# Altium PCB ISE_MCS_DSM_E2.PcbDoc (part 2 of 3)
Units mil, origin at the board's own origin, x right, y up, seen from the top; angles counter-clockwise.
Board outline 7874.02 x 2559.06 mil, 4 copper layers (Top Layer, MidLayer1, MidLayer2, Bottom Layer), stack 61.2 mil thick; 400 components, 190 nets, 1028 pads, 191 vias.
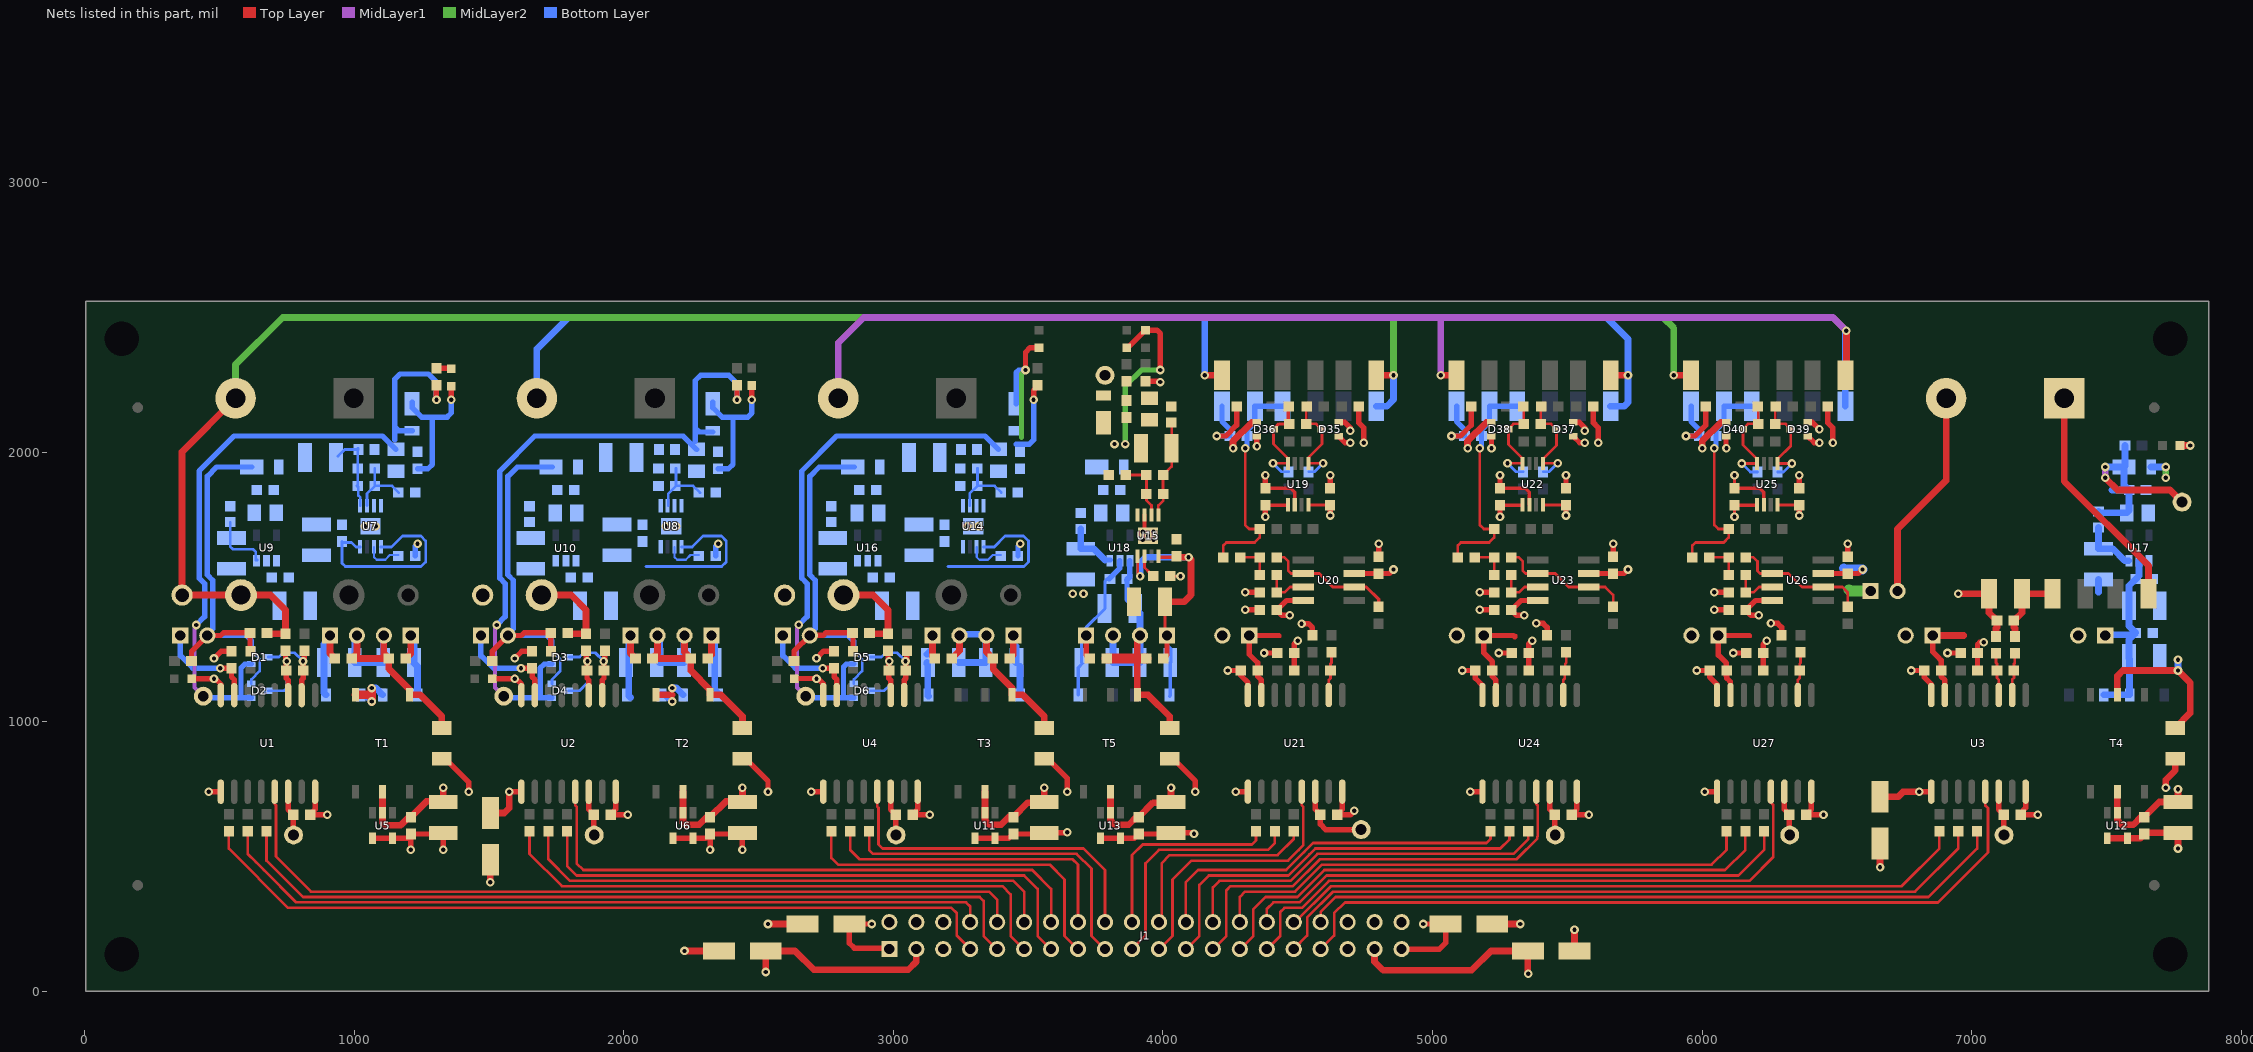
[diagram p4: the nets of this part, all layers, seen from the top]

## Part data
C1 C2 C8 C9 C32 C64: "CAP, AL, 22uF, 25V, +/-20%, 0.76 ohm, SMD"
C3 C7 C13 C15 C112 C124 C136: library part 06033C104JAT2A, "CAP, CERM, 0.1uF, 25V, +/-5%, X7R, 0603"
C4 C10 C17 C114 C126 C138: "CAP, CERM, 3900pF, 25V, +/-5%, C0G/NP0, 0603"
C5 C6 C11 C12 C14 C16 C18 C19 C20 C21 C26 C27 C29 C31 C34 C36 C41 C43 C44 C46 C53 C54 C59 C60 C68 C69 C70 C72 C74 C76 C78 C80 C85 C87 C88 C90 C97 C98 C104 C105 C106 C109 C110 C111 C115 C116 C118 C119 C120 C121 C122 C123 C127 C128 C130 C131 C132 C133 C134 C135 C139 C140 C142 C143 C144 C145: library part C0603C104K5RACTU, "CAP, CERM, 0.1uF, 50V, +/-10%, X7R, 0603"
C22 C23 C61 C62 C63: library part 202R18W102KV4E, "CAP, CERM, 1000pF, 2KV 10% X7R 1206"
C24 C25 C28 C30 C33 C35 C37 C39 C47 C48 C55 C56 C57 C58 C65 C66 C67 C71 C73 C75 C77 C79 C81 C83 C91 C92 C99 C100 C101 C102 C107 C108: library part GMK325AB7106MM-T, "CAP, CERM, 10uF, 35V, +/-20%, X7R, 1210"
C38 C40 C51 C52 C82 C84 C95 C96 C103: library part C2012X5R1H475K125AB, "CAP, CERM, 4.7uF, 50V, +/-10%, X5R, 0805"
C42 C45 C49 C50 C86 C89 C93 C94: library part 06031C103JAT2A, "CAP, CERM, 0.01uF, 100V, +/-5%, X7R, 0603"
C113 C117 C125 C129 C137 C141: library part 06031C472KAT2A, "CAP, CERM, 4700pF, 100V, +/-10%, X7R, 0603"
D1 D2 D3 D4 D5 D6 D35 D36 D37 D38 D39 D40: library part BAV99WT1G, "Diode, P-N, 70V, 0.2A, SOT-323"
D7 D8 D9 D10 D19 D20 D21 D22 D23 D24: "Diode, Schottky, 20V, 0.5A, SOD-123"
D11 D12 D15 D16 D25 D26 D29 D30 D31: library part DFLZ6V2-7, "Diode, Zener, 6.2V, 1W, PowerDI123"
D13 D14 D17 D18 D27 D28 D32 D33 D34: library part "LED_LG L29K-G2J1-24-Z", "LED SmartLED Green 570NM"
FB1 FB2 FB3 FB4 FB5 FB6 FB7 FB8 FB9: library part MMZ1608B102C, "FERRITE CHIP 1000 OHM 300MA 0603"
FID1 FID2 FID3 FID4 FID5 FID6 FID7 FID8: library part Fiducial, "Fiducial mark.  There is nothing to buy or mount."
J1: library part CONN_61304021021, "Connector, Right Angle 2x20 pin, 100mil spacing"
J2 J4 J6 J8: "Terminal Block, 4x1, 2.54mm, TH"
J3 J5 J7 J9 J10 J11 J12 J13 J14 J15 J16 J17 J18 J19 J20 J21 J22: library part JUMPER_2X100MIL, "Header, Male 2-pin, 100mil spacing,"
LBL1: library part THT-14-423-10, "Thermal Transfer Printable Labels, 0.650\" W x 0.200\" H - 10,000 per roll"
Logo1: library part TI_Logo, "Texas Instrument Corporate Signature"
MH1 MH2 MH3 MH4: library part "NY PMS 440 0025 PH", "Mountin hole, NPTH Drill 3.2mm"
R1 R4 R9 R12 R20 R29: "RES, 100 ohm, 1%, 0.1W, 0603"
R2 R10 R23: "RES 50mOHM 3W .5% TO-247 TH"
R3 R11 R24: library part RES_PWR4413DR050F, "RES METAL .005 OHM 5W 1% RADIAL"
R5 R6 R13 R14 R25 R26 R30 R31 R54 R57 R59 R63 R65 R67 R69 R72 R78 R81 R83 R85 R89 R91 R93 R96 R102 R105 R107 R109 R113 R115 R117 R120: library part CRCW06030000Z0EA, "RES, 0 ohm, 5%, 0.1W, 0603"
R7 R8 R15 R16 R27 R28 R32 R33 R73 R74 R97 R98 R121 R122: library part CRCW060310R0FKEA, "RES, 10.0 ohm, 1%, 0.1W, 0603"
R17 R18 R51 R52 R55 R70 R75 R76 R79 R94 R99 R100 R103 R118: library part RES_KTR25JZPF2204, "RES 2.2M OHM 1/3W 1% 1210"
R19 R60 R84 R108: "RES, 0 ohm, 5%, 0.1W, 0603"
R21 R61 R68 R87 R92 R111 R116: library part RES_KTR25JZPF2001, "RES 2K OHM 1/3W 1% 1210"
R22: "RES, 2.00k ohm, 0.5%, 0.1W, 0603"
R34 R35 R40 R41 R42 R43 R48 R49 R50: library part CRCW06033K90JNEA, "RES, 3.9k ohm, 5%, 0.1W, 0603"
R36 R37 R44 R45: library part RT0603BRD0737KL, "RES, 37.0k ohm, 0.1%, 0.1W, 0603"
R38 R39 R46 R47: library part CRCW060311K5FKEA, "RES, 11.5k ohm, 1%, 0.1W, 0603"
R53 R71 R77 R95 R101 R119: library part RC0603FR-0747KL, "RES 15.0K OHM 1/10W .1% SMD 0603"
R56 R66 R80 R90 R104 R114: "RES, 56.0 ohm, 1%, 0.1W, 0603"
R58 R82 R106: library part RC0603FR-071KL, "RES, 1.00k ohm, 1%, 0.1W, 0603"
R62 R64 R86 R88 R110 R112: library part RC0603FR-074K7L, "RES, 4.70k ohm, 1%, 0.1W, 0603"
T1 T2 T3 T4 T5: "Transformer 475uH SMD"
TP1 TP2 TP3 TP4 TP5 TP6 TP7 TP8 TP9 TP10 TP11 TP12: library part TP-040_RND, "Test Point, O.040 Hole"
U1 U2 U3 U4 U21 U24 U27: "20 MHz, Isolated Delta-Sigma Modulator, LVDS interface:"
U5 U6 U11 U12 U13: "Transformer Driver for Isolated Power Supplies, DBV0005A"
U7: "-36V, -200mA, Ultralow-Noise, Negative Linear Regulator"
U8 U14 U15: library part TPS7A3001DGNR, "-36V, -200mA, Ultralow-Noise, Negative Linear Regulator"
U9 U10 U16 U17 U18: "Regulator, LDO, 5V, 0.15A, SOT23-5"
U19 U22 U25: "IC, Precision, 200uA, 36V Supply Instrument Amplifier."
U20 U23 U26: library part OPA211AID, "IC, 1.1nV/vHz Noise, Low Power, Precision OpAmp"
ZZ1: library part AssemblyNoteLabel, "This Assembly Note is for PCB labels only"
ZZ2: library part AssemblyNote, "These assemblies are ESD sensitive, ESD precautions shall be observed."
ZZ3: library part AssemblyNote, "These assemblies must be clean and free from flux and all contaminants. Use of no clean flux is not acceptable."
ZZ4: library part AssemblyNote, "These assemblies must comply with workmanship standards IPC-A-610 Class 2, unless otherwise specified."

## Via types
v1: diameter 32, hole 16, Top Layer to Bottom Layer, tented both sides, 191 vias

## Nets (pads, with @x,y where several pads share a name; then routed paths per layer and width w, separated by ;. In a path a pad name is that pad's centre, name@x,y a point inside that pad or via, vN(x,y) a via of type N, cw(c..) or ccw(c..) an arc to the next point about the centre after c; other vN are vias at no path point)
+3.3V_DVDD: C1.1 C3.2 C7.2 C9.1 C13.2 C15.2 C112.2 C124.2 C136.2 J1.1 J1.39 TP1.1 TP2.1 TP3.1 TP4.1 TP10.1 TP11.1 TP12.1 U1.14 U2.14 U3.14 U4.14 U21.14 U24.14 U27.14 | length 1942.7
  Top Layer w20: U1.14@755,740.55 755,675 C3.2@775,655 ; C3.2@773.5,655 773.5,586.5 TP1.1@780,580 ; U2.14@1870,740.55 1870,675 C7.2@1890,655 ; C7.2@1888.5,655 1888.5,586.5 TP2.1@1890,585 ; v1(2920,250) C1.1@2836.61,250 2836.61,178.39 2855,160 2981.7,160 J1.1@2985.01,156.69 ; U4.14@2990,740.87 2990,675 C15.2@3010,655 ; C15.2@3008.5,655 3008.5,581.5 TP4.1@3010,580 ; U21.14@4565,740.87 4565,675 C112.2@4585,655 ; C112.2@4583.5,655 4583.5,620 4603.5,600 TP10.1@4735,600 ; J1.39@4885.01,156.69 5025,156.69 5048.39,180.08 C9.1@5048.39,250 v1(4965,250) ; U24.14@5435,740.87 5435,675 C124.2@5455,655 ; C124.2@5453.5,655 5453.5,581.5 TP11.1@5455,580 ; U27.14@6305,740.87 6305,675 C136.2@6325,655 ; C136.2@6323.5,655 6323.5,581.5 TP12.1@6325,580 ; U3.14@7100,740.87 7100,675 C13.2@7120,655 ; C13.2@7118.5,655 7118.5,581.5 TP3.1@7120,580
+5.0V_PH: C103.2 C106.1 C110.2 C111.2 C121.1 C122.2 C123.2 C133.1 C134.2 C135.2 C145.1 D31.1 D35.2 D36.2 D37.2 D38.2 D39.2 D40.2 FB9.2 J20.2 J21.2 J22.2 R50.2 R72.1 R96.1 R120.1 U19.8 U20.7 U22.8 U23.7 U25.8 U26.7 | length 1606.4
  Top Layer w12: U19.8@4540,1804.4 4619.1,1804.4 C110.2@4620,1803.5 ; U22.8@5410,1804.4 C122.2@5489.1,1804.4 ; C122.2@5494.1,1804.4 C122.2@5495,1803.5 ; U25.8@6280,1804.4 6359.1,1804.4 C134.2@6360,1803.5
  Top Layer w20: R50.2@3935,2263.5 3988.5,2263.5 3990,2265 v1(3990,2260) ; v1(4348.5,2021.5) D36.2@4348.5,2059.41 ; R72.1@4486.5,1190 C121.1@4486.5,1255 4486.5,1288.5 4497.99,1300 v1(4500,1300) ; v1(4620,1765) C110.2@4620,1803.5 ; D35.2@4651.5,2110.59 4674.41,2110.59 4695,2090 v1(4695,2080) ; U20.7@4709,1550 4840,1550 v1(4855,1565) ; v1(5218.5,2015) D38.2@5218.5,2059.41 ; R96.1@5356.5,1190 C133.1@5356.5,1255 5356.5,1288.5 5367.99,1300 v1(5370,1300) ; v1(5495,1765) C122.2@5495,1803.5 ; D37.2@5521.5,2110.59 5544.41,2110.59 5565,2090 v1(5565,2080) ; U23.7@5579,1550 5710,1550 v1(5725,1565) ; D40.2@6088.5,2059.41 6088.5,2021.5 6085,2017.99 6085,2015 v1(6090,2015) ; R120.1@6226.5,1190 C145.1@6226.5,1255 6226.5,1286.5 v1(6240,1300) ; v1(6360,1765) C134.2@6360,1803.5 ; D39.2@6391.5,2110.59 6409.41,2110.59 v1(6435,2085) ; U26.7@6449,1550 6580,1550 v1(6595,1565)
  Bottom Layer w36: 6525,1570 6530,1565 v1(6595,1565)
+5.0V_USH: C6.1 C51.2 C53.1 D1.2 D2.2 D15.1 FB3.2 J3.2 R6.1 R40.2 | length 1491.7
  Top Layer w20: R40.2@396.5,1225 396.5,1261.5 J3.2@455,1320 505,1320 515,1330 C6.1@613.5,1330 ; C6.1@613.5,1320 613.5,1262.99 R6.1@615,1261.5
  Bottom Layer w10: D2.2@618.5,1140.59 618.5,1156.85 649.25,1187.6 649.25,1232.43 618.5,1263.18 D1.2@618.5,1265.59
  Bottom Layer w20: J3.2@450,1320 J3.2@455,1325 ; D1.2@618.5,1265.59 618.5,1301.5 600,1320 J3.2@455,1320 J3.2@455,1325 ; D15.1@620,1945 D15.1@619.81,1945 490,1945 455,1910 455,1545 475,1525 475,1345 J3.2@455,1325
+5.0V_VDC: C19.1 C96.2 C98.1 D30.1 FB8.2 J9.2 R26.1 R49.2 TP9.1 | length 988.8
  Top Layer w20: R26.1@7021.5,1190 C19.1@7021.5,1255 7021.5,1286.5 7030,1295 v1(7045,1295)
  Top Layer w25: v1(7495,1905) 7540,1860 7735,1860 TP9.1@7780,1815
  MidLayer1 w25: v1(7495,1905) v1(7495,1945)
  Bottom Layer w25: FB8.2@7470,1779.53 7474.53,1775 C96.2@7575,1775 7583.5,1783.5 C98.1@7583.5,1860 ; v1(7495,1945) D30.1@7564.8,1945 ; 7520,1860 C98.1@7583.5,1860 ; R49.2@7568.5,2025 7568.5,1948.7 D30.1@7564.8,1945 ; D30.1@7564.8,1945 7564.8,1878.7 C98.1@7583.5,1860
+5.0V_VSH: C12.1 C52.2 C54.1 D3.2 D4.2 D16.1 FB4.2 J5.2 R14.1 R41.2 | length 1484.4
  Top Layer w20: R41.2@1511.5,1225 1511.5,1261.5 J5.2@1570,1320 1620,1320 1630,1330 C12.1@1728.5,1330 ; C12.1@1728.5,1320 1728.5,1262.99 R14.1@1730,1261.5
  Bottom Layer w10: D4.2@1733.5,1140.59 1733.5,1156.85 1764.25,1187.6 1764.25,1232.43 1733.5,1263.18 D3.2@1733.5,1265.59
  Bottom Layer w20: D3.2@1733.5,1265.59 1733.5,1301.5 1715,1320 J5.2@1570,1320 1570,1325 1590,1345 1590,1525 1570,1545 1570,1910 1605,1945 D16.1@1734.81,1945
+5.0V_WSH: C21.1 C95.2 C97.1 D5.2 D6.2 D29.1 FB7.2 J10.2 R31.1 R48.2 | length 1485.6
  Top Layer w20: R48.2@2631.5,1225.31 2631.5,1261.81 2690,1320.31 2740,1320.31 2750,1330.31 C21.1@2848.5,1330.31 ; R31.1@2850,1261.5 C21.1@2850,1328.5
  Bottom Layer w10: D6.2@2853.5,1140.59 2853.5,1156.85 2884.25,1187.6 2884.25,1232.43 2853.5,1263.18 D5.2@2853.5,1265.59
  Bottom Layer w20: J10.2@2690,1320 2832.01,1320 2853.5,1298.5 D5.2@2853.5,1265.59 ; J10.2@2690,1325 2710,1345 2710,1525 2690,1545 2690,1910 2725,1945 D29.1@2854.81,1945
+5V_CNTL: C2.1 C8.1 C24.2 C25.2 C26.2 C27.2 C32.1 C64.1 C65.2 C66.2 C67.2 C68.2 C69.2 C70.2 J1.3 J1.37 T1.2 T2.2 T3.2 T4.2 T5.2 U5.2 U6.2 U11.2 U12.2 U13.2 | length 3766.9
  Top Layer w25: T1.2@1105,740 U5.2@1105,662.24 1105,625 1113.44,616.56 1172.85,616.56 1201.29,645 C26.2@1205,645 ; C26.2@1210,646.5 1268.5,705 C24.2@1330,705 ; C24.2@1330,702.09 C24.2@1330,705 ; v1(1330,755) C24.2@1330,705 ; v1(1505,405) C32.1@1505,488.39 ; T2.2@2220,740 U6.2@2220,662.24 2220,625 2226.91,618.09 2279.52,618.09 2307.92,646.5 C27.2@2320,646.5 2378.5,705 C25.2@2440,705 ; C25.2@2440,702.09 C25.2@2440,705 ; v1(2440,755) C25.2@2440,705 ; v1(2526.61,71.61) C2.1@2526.61,150 2635,150 2705,80 3055,80 3085.01,110.01 J1.3@3085.01,156.69 ; T3.2@3340,740 U11.2@3340,662.24 3340,633.38 3355.29,618.09 3399.52,618.09 3427.92,646.5 C68.2@3441.5,646.5 ; C68.2@3445,650 C68.2@3441.5,646.5 ; C65.2@3560,700 3498.5,700 C68.2@3445,646.5 C68.2@3441.5,646.5 ; C65.2@3560,702.09 v1(3560,755) ; T5.2@3805,740 U13.2@3805,662.24 3805,635 3807.11,632.89 3807.11,631.27 3820.29,618.09 3873.09,618.09 3901.5,646.5 C70.2@3910,646.5 3963.5,700 C67.2@4030,700 ; C67.2@4030,702.09 v1(4030,755) ; J1.37@4785.01,156.69 4785.01,109.99 4816.61,78.39 5145,78.39 5216.61,150 C8.1@5353.39,150 5353.39,66.61 v1(5355,65) ; v1(6660,460) C64.1@6660,548.39 ; T4.2@7540,740 U12.2@7540,662.24 7540,633.38 7555.29,618.09 7599.52,618.09 7627.92,646.5 C69.2@7640,646.5 7695.59,702.09 C66.2@7765,702.09 v1(7765,750)
  Bottom Layer w25: v1@2525,70 v1(2526.61,71.61)
+6V_PH: C75.1 C76.1 C107.2 C109.1 D21.1 J19.1 U18.2 | length 645.2
  Top Layer w20: J19.1@3715,1320 3715,1248.5 C76.1@3728.5,1235
  Bottom Layer w12: 3685,1145 3685.53,1145 ; D21.1@3685.53,1100 3685.53,1145 ; C75.1@3697.91,1220 3697.91,1297.91 J19.1@3720,1320 ; C75.1@3701.46,1216.46 3685.53,1200.53 3685.53,1145 ; J19.1@3715,1320 3715,1350 C107.2@3785,1420 ; C107.2@3785,1425 3785,1521.5 C109.1@3793.5,1530
  Bottom Layer w20: C109.1@3800,1530 3826.81,1556.81 3826.81,1556.99 3840,1570.17 U18.2@3840,1597.76
+6V_USH: C28.1 C29.1 C55.2 C59.1 D7.1 J13.1 U9.2 | length 321.8
  Top Layer w25: J13.1@910,1320 910,1253.5 C29.1@928.5,1235
  Bottom Layer w25: D7.1@895,1100 887.91,1107.09 C28.1@887.91,1220 887.91,1287.91 J13.1@915,1315
+6V_VDC: C73.1 C74.1 C101.2 C105.1 D20.1 D22.1 J18.1 U17.2 | length 739.6
  Bottom Layer w25: D20.1@7489.47,1100 D22.1@7585.53,1100 7585.53,1232.38 C73.1@7582.91,1235 7582.91,1304.41 C74.1@7601.75,1323.25 ; J18.1@7495,1320 7498.25,1323.25 C74.1@7601.75,1323.25 ; U17.2@7620,1597.76 7620,1541.5 C105.1@7608.5,1530 7582.91,1504.41 C101.2@7582.91,1430 7582.91,1355.59 C74.1@7608.5,1330 C74.1@7601.75,1323.25
+6V_VSH: C30.1 C31.1 C57.2 C60.1 D8.1 J14.1 U10.2 | length 333.5
  Top Layer w25: J14.1@2025,1320 2025,1253.5 C31.1@2043.5,1235
  Bottom Layer w25: D8.1@2025,1090 2017.91,1097.09 2017.91,1220 2017.91,1317.91 J14.1@2025,1325
+6V_WSH: C71.1 C72.1 C99.2 C104.1 D19.1 J17.1 U16.2 | length 297.7
  Top Layer w25: J17.1@3145,1320 3145,1243.5 C72.1@3153.5,1235
  Bottom Layer w25: C71.1@3125,1215 C71.1@3125,1220 ; C71.1@3125,1250 3145,1270 J17.1@3145,1320 J17.1@3145,1325 ; C71.1@3127.91,1215 3127.91,1097.09 D19.1@3130,1095
-5.0V_PH: C84.2 C90.1 C116.2 C119.2 C128.2 C131.2 C140.2 C143.2 D26.2 D35.1 D36.1 D37.1 D38.1 D39.1 D40.1 FB6.2 R43.2 TP8.1 U19.5 U20.4 U22.5 U23.4 U25.5 U26.4 | length 1481.1
  Top Layer w12: C119.2@4380,1803.5 4462.3,1803.5 U19.5@4463.2,1804.4 ; C131.2@5250,1803.5 5332.3,1803.5 U22.5@5333.2,1804.4 ; v1(6120,1760) C143.2@6120,1803.5 6202.3,1803.5 U25.5@6203.2,1804.4
  Top Layer w20: v1(4380,1760) C119.2@4380,1803.5 ; v1(4470,1395) 4441.5,1395 C116.2@4421.5,1415 4423.17,1415 4458.17,1450 U20.4@4520,1450 ; D35.1@4651.5,2059.41 4675.91,2035 v1(4695,2035) ; v1(5250,1760) C131.2@5250,1803.5 ; v1(5340,1395) 5311.5,1395 C128.2@5291.5,1415 5293.17,1415 5328.17,1450 U23.4@5390,1450 ; D37.1@5521.5,2059.41 5545.91,2035 v1(5565,2035) ; v1(6210,1395) 6181.5,1395 C140.2@6161.5,1415 6163.17,1415 6198.17,1450 U26.4@6260,1450 ; D39.1@6391.5,2059.41 6415.91,2035 v1(6435,2035)
  Top Layer w25: v1(4260,2015) 4260,2040.81 4329.78,2110.59 D36.1@4348.5,2110.59 ; v1(5130,2015) 5130,2040.81 5199.78,2110.59 D38.1@5218.5,2110.59 ; v1(6000,2015) 6000,2040.81 6069.78,2110.59 D40.1@6088.5,2110.59
-5.0V_USH: C38.2 C43.1 D1.1 D2.1 D11.2 FB1.2 R34.2 TP5.1 | length 2602.8
  Top Layer w20: v1(1305,2195) R34.2@1305,2248.5
  MidLayer1 w15: v1(414,1359) 407.5,1352.5 407.5,1127.5 TP5.1@440,1095
  Bottom Layer w20: v1(414,1359) 445,1390 445,1512.57 425,1532.57 425,1930.29 554.71,2060 1105,2060 C38.2@1155,2010 ; TP5.1@440,1095 445.59,1089.41 D2.1@618.5,1089.41 ; 580,1090 580,1200 594.41,1214.41 D1.1@618.5,1214.41 ; 1150,2045 1150,2095 ; D11.2@1215,2079.8 1165.2,2079.8 1150,2095 ; v1(1305,2195) 1305,2260 1275,2290 1170,2290 1150,2270 1150,2095
-5.0V_VSH: C40.2 C46.1 D3.1 D4.1 D12.2 FB2.2 R35.2 TP6.1 | length 2607.1
  Top Layer w20: v1(2420,2195) R35.2@2420,2248.5
  MidLayer1 w15: v1(1529,1359) 1522.5,1352.5 1522.5,1127.5 TP6.1@1555,1095
  Bottom Layer w20: v1(1529,1359) 1560,1390 1560,1512.57 1540,1532.57 1540,1930.29 1669.71,2060 2220,2060 C40.2@2270,2010 ; TP6.1@1555,1095 1560.59,1089.41 D4.1@1733.5,1089.41 ; 1690,1090 1690,1198.82 1705.59,1214.41 D3.1@1733.5,1214.41 ; 2265,2040.2 2265,2090.2 ; D12.2@2330,2075 2280.2,2075 2265,2090.2 ; v1@2420,2190.2 2420,2255.2 2390,2285.2 2285,2285.2 2265,2265.2 2265,2090.2
-5.0V_WSH: C82.2 C87.1 D5.1 D6.1 D25.2 FB5.2 R42.2 TP7.1 | length 2297.6
  Top Layer w20: v1(3520,2195) 3520,2228.5 R42.2@3540,2248.5
  MidLayer1 w15: v1(2649,1359.31) 2642.5,1352.81 2642.5,1127.81 TP7.1@2675,1095.31
  Bottom Layer w20: v1@2649,1359 2680,1390 2680,1512.57 2660,1532.57 2660,1930.29 2789.71,2060 3340,2060 C82.2@3390,2010 ; TP7.1@2675,1095 2680.59,1089.41 D6.1@2853.5,1089.41 ; 2815,1090 2815,1203.82 2825.59,1214.41 D5.1@2853.5,1214.41 ; 3455,2029.8 3504.8,2029.8 3520,2045 v1(3520,2195)
-6V_PH: C79.2 C80.2 C83.2 C88.1 D24.2 J16.1 U15.5 U15.8 | length 1135.9
  Top Layer w10: U15.5@3906.2,1613.4 3906.2,1543.8 v1@3915,1535
  Top Layer w12: U15.8@3983,1613.4 3986.4,1610 C88.1@4050,1610 ; J16.1@4015,1320 4007.09,1327.91 C83.2@4007.09,1445 C83.2@4015,1445
  Top Layer w20: C80.2@4001.5,1235 4015,1248.5 J16.1@4015,1320
  Top Layer w25: C83.2@4015,1445 4077.6,1445 4103.5,1470.9 4103.5,1601.5 v1(4095,1610) 4053.5,1610 C88.1@4050,1613.5
  Bottom Layer w12: J16.1@4015,1320 4015,1285 4030,1270 C79.2@4030,1220 ; D24.2@4025,1095 4027.09,1097.09 C79.2@4027.09,1220
  Bottom Layer w25: v1(3915,1540) 3915,1590 3935,1610 v1(4095,1610)
-6V_USH: C33.2 C34.2 C37.2 C41.1 D9.2 J11.1 U7.5 U7.8 | length 1056.4
  Top Layer w25: C34.2@1191.5,1235 1210,1253.5 J11.1@1210,1320
  Bottom Layer w10: C41.1@955,1668.5 C41.1@955,1665 ; U7.8@1022,1648.4 1006.6,1648.4 990,1665 C41.1@955,1665 ; U7.5@1098.8,1648.4 1138.4,1648.4 1179,1689 1247.01,1689 1265,1671.01 1265,1593 1248,1576 967,1576 955,1588 C41.1@955,1665
  Bottom Layer w25: C33.2@1220,1220 1234.47,1205.53 D9.2@1234.47,1100 ; C33.2@1222.09,1220 J11.1@1222.09,1312.91
-6V_VSH: C35.2 C36.2 C39.2 C44.1 D10.2 J12.1 U8.5 U8.8 | length 887.4
  Top Layer w25: C36.2@2311.5,1235 2325,1248.5 J12.1@2325,1320
  Bottom Layer w10: 2082,1576 2363,1576 2380,1593 2380,1671.01 2362.01,1689 2294,1689 2253.4,1648.4 U8.5@2213.8,1648.4
  Bottom Layer w25: J12.1@2330,1320 2337.09,1312.91 C35.2@2337.09,1220 2337.09,1117.91 D10.2@2350,1105
-6V_WSH: C77.2 C78.2 C81.2 C85.1 D23.2 J15.1 U14.5 U14.8 | length 870.3
  Top Layer w25: C78.2@3431.5,1235 3445,1248.5 J15.1@3445,1320
  Bottom Layer w10: 3202.8,1576 3483.8,1576 3500.8,1593 3500.8,1671.01 3482.81,1689 3414.8,1689 3374.2,1648.4 U14.5@3334.6,1648.4
  Bottom Layer w25: J15.1@3445,1320 3445,1290 3455,1280 C77.2@3455,1225 ; C77.2@3455,1220 C77.2@3456.04,1218.96 ; D23.2@3469.47,1100 C77.2@3469.47,1205.53
CLKN_CH_U: J1.9 R5.2 | length 3031.3
  Top Layer w10: R5.2@675,593.5 675,485 810,350 3320,350 3335,335 3335,205 J1.9@3385,155
CLKN_CH_V: J1.13 R13.2 | length 2155.9
  Top Layer w10: R13.2@1790,595 R13.2@1790,593.5 1790,465 1825,430 3485,430 3535,380 3535,205 J1.13@3585,155
CLKN_CH_W: J1.17 R30.2 | length 1243.2
  Top Layer w10: R30.2@2910,593.5 2910,525 2925,510 3680,510 3735,455 3735,205 J1.17@3785,155
CLKN_U_PH: J1.22 R69.2 | length 779.7
  Top Layer w10: J1.22@3985.01,256.69 3995,266.68 3995,475 4025,505 4425,505 4485,565 R69.2@4485,593.5 R69.2@4485,595
CLKN_V_PH: J1.26 R93.2 | length 1398.2
  Top Layer w10: J1.26@4185,260 4185,385 4210,410 4473.58,410 4573.28,509.7 4573.28,510 5300,510 5355,565 R93.2@5355,593.5
CLKN_VDC: J1.34 R25.2 | length 2625.6
  Top Layer w10: J1.34@4585.01,256.69 4585.01,295 4639.85,349.84 6839.84,349.84 7020,530 R25.2@7020,585
CLKN_W_PH: J1.30 R117.2 | length 2059.6
  Top Layer w10: J1.30@4385,250 4385,305 4410,330 4506.72,330 4606.72,430 6135,430 6230,525 R117.2@6230,593.5
CLKP_CH_U: J1.10 U1.13 | length 3078.3
  Top Layer w10: U1.13@705,750 U1.13@705,740.55 705,695 710,690 710,500 840,370 3355,370 3385,340 J1.10@3385,255
CLKP_CH_V: J1.14 U2.13 | length 2199.7
  Top Layer w10: U2.13@1820,750 U2.13@1820,740.55 1820,690 1825,685 1825,475 1850,450 3515,450 3585.01,379.99 J1.14@3585.01,256.69
CLKP_CH_W: J1.18 U4.13 | length 1272.3
  Top Layer w10: U4.13@2940,740.87 2940,686.1 2945,681.1 2945,545 2960,530 3705,530 3785,450 J1.18@3785,255
CLKP_U_PH: J1.21 U21.13 | length 1028.8
  Top Layer w10: J1.21@3985,155 4035,205 4035,415 4105,485 4463.73,485 4503.28,524.55 4503.28,524.85 4520,541.57 4520,685 4515,690 U21.13@4515,740.87 U21.13@4515,750
CLKP_V_PH: J1.25 U24.13 | length 1650.1
  Top Layer w10: J1.25@4185,155 4235,205 4235,375 4250,390 4481.86,390 4581.86,490 5311.1,490 5388.7,567.61 5388.7,573.7 5390,575 5390,690 5385,695 U24.13@5385,740.87
CLKP_VDC: J1.33 U3.13 | length 2902.2
  Top Layer w10: J1.33@4585.01,156.69 4635,206.68 4635,290 4674.84,329.84 6874.84,329.84 7060,515 7060,680 7050,690 U3.13@7050,740.87
CLKP_W_PH: J1.29 U27.13 | length 2318.7
  Top Layer w10: J1.29@4385,155 4435,205 4435,295 4450,310 4515,310 4615,410 6175,410 6263.7,498.7 6263.7,691.1 6255,699.8 U27.13@6255,740
DCLINK_N: C16.1 C18.2 C19.2 C62.2 C73.2 C74.2 C96.1 C98.2 C101.1 C102.1 C105.2 D30.2 D33.1 J6.2 J7.2 J18.2 R21.2 R22.1 T4.5 U3.8 U17.1 | length 2012.6
  Top Layer w20: v1(6775,1190) C18.2@6823.5,1190 6823.5,1165.51 6850,1139.01 U3.8@6850,1099.13 ; v1(6910,1255) C19.2@6958.5,1255
  Top Layer w25: J7.2@6725,1485 6725,1715 6905,1895 J6.2@6905,2160 ; v1(6950,1475) R21.2@7063.98,1475 7063.98,1404.53 C16.1@7093.5,1375 7093.5,1350.3 7090,1346.8 R22.1@7090,1316.5 ; T4.5@7540,1099.84 7540,1170 7560,1190 v1(7765,1190) 7810,1145 7810,1032.09 C62.2@7755,977.09 ; D33.1@7772.48,2025 v1(7810,2025)
  MidLayer2 w25: v1(7720,1905) v1(7720,1945)
  Bottom Layer w25: 7470,1480 C102.1@7470,1527.91 ; D30.2@7665.2,1945 v1(7720,1945) ; v1(7765,1190) v1(7765,1230)
DCLINK_P: J6.1 R17.1 | length 814.7
  Top Layer w25: J6.1@7343,2160 7343,1892 7656.02,1578.98 R17.1@7656.02,1475
DGND: C1.2 C2.2 C3.1 C7.1 C8.2 C9.2 C13.1 C15.1 C22.1 C23.1 C24.1 C25.1 C26.1 C27.1 C32.2 C61.1 C62.1 C63.1 C64.2 C65.1 C66.1 C67.1 C68.1 C69.1 C70.1 C112.1 C124.1 C136.1 J1.2 J1.4 J1.5 J1.6 J1.35 J1.36 J1.38 J1.40 U1.9 U1.16 U2.9 U2.16 U3.9 U3.16 U4.9 U4.16 U5.4 U5.5 U6.4 U6.5 U11.4 U11.5 U12.4 U12.5 U13.4 U13.5 U21.9 U21.16 U24.9 U24.16 U27.9 U27.16 | length 4767.3
  Top Layer w20: v1(460,740) 460.55,740.55 U1.9@505,740.55 ; C3.1@830,650 855,675 U1.16@855,740.55 ; C3.1@836.5,655 v1(900,655) ; U5.4@1067.6,567.76 U5.5@1142.4,567.76 1197.76,567.76 C26.1@1210,580 ; v1(1210,525) C26.1@1210,580 ; C24.1@1325,585 1323.5,583.5 C26.1@1210,583.5 C26.1@1210,580 ; C22.1@1325,862.91 1337.09,862.91 1425,775 v1(1425,740) ; v1(1330,525) C24.1@1330,587.91 ; v1(1575,740) 1575.55,740.55 U2.9@1620,740.55 ; C7.1@1950,655 1970,675 U2.16@1970,740.55 ; C7.1@1951.5,655 v1(2015,655) ; U6.4@2182.6,567.76 2252.24,567.76 U6.5@2255,565 ; U6.5@2257.4,567.76 2302.76,567.76 C27.1@2320,585 ; v1(2320,525) C27.1@2320,583.5 C25.1@2440,583.5 ; v1(2440,525) C25.1@2440,583.5 ; C25.1@2440,587.91 C25.1@2440,583.5 ; C23.1@2440,862.91 2452.09,862.91 2535,780 v1(2535,740) ; v1(2695,740) 2695.87,740.87 U4.9@2740,740.87 ; C15.1@3070,655 3090,675 U4.16@3090,740.87 ; C15.1@3071.5,655 v1(3135,655) ; U11.4@3302.6,567.76 3372.76,567.76 U11.5@3375,570 ; U11.5@3377.4,567.76 3427.76,567.76 C68.1@3445,585 ; C68.1@3445,583.5 3563.5,583.5 C65.1@3565,585 ; C65.1@3560,587.91 3642.91,587.91 v1(3645,590) ; C61.1@3560,862.91 3572.09,862.91 3645,790 v1(3645,740) ; U13.4@3767.6,567.76 3837.76,567.76 U13.5@3840,570 ; U13.5@3842.4,567.76 3892.76,567.76 C70.1@3910,585 ; C70.1@3910,583.5 4028.5,583.5 C67.1@4030,585 ; C63.1@4025,862.91 4037.09,862.91 4120,780 v1(4120,740) ; C67.1@4030,587.91 4112.09,587.91 v1(4115,585) ; v1(4270,740) 4270.87,740.87 U21.9@4315,740.87 ; C112.1@4645,655 4665,675 U21.16@4665,740.87 ; C112.1@4646.5,655 4695,655 v1(4710,670) ; v1(5140,740) 5140.87,740.87 U24.9@5185,740.87 ; C124.1@5515,655 5535,675 U24.16@5535,740.87 ; C124.1@5516.5,655 v1(5580,655) ; v1(6010,740) 6010.87,740.87 U27.9@6055,740.87 ; C136.1@6385,655 6405,675 U27.16@6405,740.87 ; C136.1@6386.5,655 v1(6450,655) ; v1(6805,740) 6805.87,740.87 U3.9@6850,740.87 ; C13.1@7180,660 7200,680 U3.16@7200,740.87 ; C13.1@7181.5,655 v1(7245,655)
  Top Layer w25: C32.2@1505,661.61 1556.61,661.61 1575,680 v1(1575,740) ; v1(2225,150) C2.2@2353.39,150 ; v1(2535,250) C1.2@2663.39,250 ; C9.2@5221.61,250 v1(5325,250) ; C8.2@5526.61,150 v1(5526.61,228.39) ; C64.2@6660,721.61 6726.61,721.61 6745,740 v1(6805,740) ; U12.4@7502.6,567.76 U12.5@7577.4,567.76 7624.25,567.76 C69.1@7640,583.5 7644.41,587.91 C66.1@7765,587.91 v1(7765,530) ; v1(7720,755) 7720,785 7755,820 C62.1@7755,862.91
  Bottom Layer w25: v1(7720,755) v1@7725,755
DOUTN_CH_U: J1.7 R8.2 | length 3016.9
  Top Layer w10: R8.2@535,593.5 535,530 755,310 3215,310 3235,290 3235,206.7 J1.7@3285.01,156.69
DOUTN_CH_V: J1.11 R16.2 | length 2156.3
  Top Layer w10: R16.2@1650,593.5 1650,510 1770,390 3405,390 3435,360 3435,205 J1.11@3485,155
DOUTN_CH_W: J1.15 R33.2 | length 1281.5
  Top Layer w10: R33.2@2780,593.5 2770,583.5 2770,495 2795,470 3580,470 3635,415 3635,205 J1.15@3685,155
DOUTN_U_PH: J1.20 R74.2 | length 766.3
  Top Layer w10: J1.20@3885,255 3885,505 3925,545 4330,545 4345,560 R74.2@4345,593.5
DOUTN_V_PH: J1.24 R98.2 | length 1376.4
  Top Layer w10: J1.24@4085,255 4085,405 4130,450 4457.01,450 4523.28,516.27 4523.28,516.57 4556.71,550 5200,550 5215,565 R98.2@5215,593.5 R98.2@5215,595
DOUTN_VDC: J1.32 R28.2 | length 2573.4
  Top Layer w10: J1.32@4485.01,256.69 4490.13,256.69 4623.28,389.84 ; 4623.28,390 4623.28,389.84 ; R28.2@6880,595 R28.2@6880,593.5 6880,530 6739.84,389.84 4623.28,389.84
DOUTN_W_PH: J1.28 R122.2 | length 2042.5
  Top Layer w10: J1.28@4285,255 4285,350 4305,370 4490.15,370 4590.15,470 5485,470 6035,470 6090,525 R122.2@6090,593.5 ; R122.2@6095,593.5 R122.2@6095,595
DOUTP_CH_U: J1.8 R7.2 | length 2905.3
  Top Layer w10: R7.2@605,593.5 605,510 635,480 ; 635.09,480.09 637.2,477.97 637.2,477.63 665.43,449.4 665.6,449.4 ; 665,450 665.6,449.4 ; J1.8@3285,255 3285,315 3270,330 785,330 665.6,449.4
DOUTP_CH_V: J1.12 R15.2 | length 2031.5
  Top Layer w10: R15.2@1720,593.5 1720,490 1800,410 3445,410 3485.01,369.99 J1.12@3485.01,256.69
DOUTP_CH_W: J1.16 R32.2 | length 1151.3
  Top Layer w10: R32.2@2840,593.5 2840,525 2875,490 3665,490 3685,470 J1.16@3685,255
DOUTP_U_PH: J1.19 R73.2 | length 893.6
  Top Layer w10: J1.19@3885.01,156.69 3935,206.68 3935,475 3985,525 4390,525 4415,550 R73.2@4415,593.5
DOUTP_V_PH: J1.23 R97.2 | length 1510.4
  Top Layer w10: J1.23@4085,155 4135,205 4135,395 4170,430 4465.29,430 4543.28,507.98 4543.28,508.28 4564.99,530 5251.02,530 5285,563.98 R97.2@5285,593.5
DOUTP_VDC: J1.31 R27.2 | length 2718.6
  Top Layer w10: J1.31@4485.01,156.69 4535,206.68 4535,273.28 4631.57,369.84 6789.84,369.84 6950,530 R27.2@6950,590
DOUTP_W_PH: J1.27 R121.2 | length 2155.3
  Top Layer w10: J1.27@4285,155 4335,205 4335,305 4380,350 4498.43,350 4598.43,450 6085,450 6160,525 R121.2@6160,593.5
GND_PH: C63.2 C75.2 C76.2 C79.1 C80.1 C83.1 C84.1 C88.2 C90.2 C92.1 C94.1 C103.1 C106.2 C107.1 C108.1 C109.2 C110.1 C111.1 C116.1 C117.2 C118.1 C119.1 C120.2 C121.2 C122.1 C123.1 C128.1 C129.2 C130.1 C131.1 C132.2 C133.2 C134.1 C135.1 C140.1 C141.2 C142.1 C143.1 C144.2 C145.2 D26.1 D28.2 D31.2 D34.1 J7.1 J16.2 J19.2 R47.1 R53.2 R67.2 R68.2 R71.1 R77.2 R91.2 R92.2 R95.1 R101.2 R115.2 R116.2 R119.1 T5.4 U15.3 U15.4 U15.9 U18.1 U19.6 U21.8 U22.6 U24.8 U25.6 U27.8 | length 5533.6
  Top Layer w10: C94.1@4021.5,1540 v1(4065,1540)
  Top Layer w12: C119.1@4380,1866.5 4473.5,1866.5 4488.8,1851.2 U19.6@4488.8,1804.4 ; C131.1@5250,1866.5 5343.5,1866.5 5358.8,1851.2 U22.6@5358.8,1804.4 ; v1(6120,1915) C143.1@6120,1866.5 6213.5,1866.5 6228.8,1851.2 U25.6@6228.8,1804.4
  Top Layer w15: U15.9@3931.8,1702.4 U15.3@3931.8,1767
  Top Layer w20: D28.2@3865,2387.52 3870.04,2387.52 D34.1@3935,2452.48 3977.52,2452.48 3990,2440 v1(3990,2305) ; U15.9@3931.8,1702.4 v1(3944.2,1690) ; v1(4200,2060) 4233.23,2060 4273.5,2100.27 R71.1@4273.5,2170 ; v1(4240,1190) C120.2@4288.5,1190 4288.5,1171.5 4315,1145 U21.8@4315,1099.13 ; v1(4305,1415) C116.1@4358.5,1415 ; v1(4305,1480) C117.2@4358.5,1480 ; v1(4375,1255) C121.2@4423.5,1255 ; C119.1@4380,1866.5 v1(4380,1915) ; v1(4514.1,1364.1) 4539.09,1364.1 4554.1,1349.09 R67.2@4554.1,1320.6 ; C110.1@4620,1866.5 v1(4620,1915) ; R53.2@4726.5,2170 4726.5,2109.42 4731,2104.91 4731,2104 4745,2090 v1(4745,2035) ; C111.1@4800,1611.5 v1(4800,1660) ; v1(5070,2060) 5103.23,2060 5143.5,2100.27 R95.1@5143.5,2170 ; v1(5110,1190) C132.2@5158.5,1190 5158.5,1161.5 5185,1135 U24.8@5185,1099.13 ; v1(5175,1415) C128.1@5228.5,1415 ; v1(5175,1480) C129.2@5228.5,1480 ; v1(5245,1255) C133.2@5293.5,1255 ; C131.1@5250,1866.5 v1(5250,1915) ; v1(5385,1365) 5409.98,1365 5425,1349.98 R91.2@5425,1321.5 ; C122.1@5495,1866.5 v1(5495,1915) ; R77.2@5596.5,2170 5596.5,2109.42 5601,2104.91 5601,2104 5615,2090 v1(5615,2035) ; C123.1@5670,1611.5 v1(5670,1660) ; v1(5940,2060) 5973.23,2060 6013.5,2100.27 R119.1@6013.5,2170 ; v1(5980,1190) C144.2@6028.5,1190 ; C144.2@6027.52,1190.99 6027.52,1166.5 6054.01,1140 6054.01,1100.12 U27.8@6055,1099.13 ; v1(6045,1415) C140.1@6098.5,1415 ; v1(6045,1480) C141.2@6098.5,1480 ; v1(6115,1255) C145.2@6163.5,1255 ; v1(6255,1365) 6279.98,1365 6295,1349.98 R115.2@6295,1321.5 ; C134.1@6360,1866.5 v1(6360,1915) ; R101.2@6466.5,2170 6466.5,2108.5 6485,2090 v1(6485,2035) ; C135.1@6540,1611.5 v1(6540,1660)
  Top Layer w25: J16.2@3915,1320 3905,1310 3905,1235 T5.4@3905,1099.84 3945.16,1099.84 4025,1020 C63.2@4025,977.09 C63.2@4025,975
  Top Layer w37.5: C76.2@3791.5,1235 3905,1235 C80.1@3938.5,1235
  MidLayer2 w20: v1(3860,2030) 3860,2245 3920,2305 v1(3990,2305)
  MidLayer2 w40: 6545,1490 6550,1485 J7.1@6625,1485
  Bottom Layer w20: C109.2@3865,1525 C109.2@3866.5,1526.5 ; C109.2@3866.5,1530 C109.2@3866.5,1526.5 ; U18.1@3877.4,1597.76 3877.4,1537.4 C109.2@3866.5,1526.5 ; C107.1@3900,1420 3866.5,1453.5 C109.2@3866.5,1526.5 ; v1(4200,2060) C118.1@4248.5,2060 4248.5,2084.7 4218.98,2114.22 R68.2@4218.98,2170 ; v1(5070,2060) C130.1@5118.5,2060 5118.5,2084.7 5088.98,2114.22 R92.2@5088.98,2170 ; v1(5940,2060) C142.1@5988.5,2060 5988.5,2084.7 5958.98,2114.22 R116.2@5958.98,2170
  Bottom Layer w25: J19.2@3815,1320 3815,1220 C79.1@3912.91,1220 3915,1220 J16.2@3915,1320 3915,1402.09 C107.1@3897.09,1420
  other v1: 3665,1475 3705,1475 3925,1675 3965,1675 3925,1705 3965,1705 3820,2030
GND_USH: C5.2 C6.2 C22.2 C28.2 C29.2 C33.1 C34.1 C37.1 C38.1 C41.2 C43.2 C47.1 C49.1 C51.1 C53.2 C55.1 C56.1 C59.2 D11.1 D13.2 D15.2 D17.1 J2.2 J11.2 J13.2 R2.2 R3.2 R4.1 R38.1 R51.1 R52.1 R118.2 T1.4 U1.8 U7.3 U7.4 U7.9 U9.1 | length 9411.1
  Top Layer w20: D17.1@397.48,1160 v1(480,1160) ; v1(480,1235) 506.5,1261.5 C5.2@545,1261.5 ; v1@482.5,1162.5 505,1140 U1.8@505,1098.82 ; v1(1360,2195) D13.2@1360,2244.52
  Top Layer w25: J2.2@560,2200 361.42,2001.42 R3.2@361.42,1470 R2.2@580,1470 690,1470 745,1415 R4.1@745,1326.5 C6.2@680,1326.5 ; C29.2@991.5,1235 1010,1253.5 J13.2@1010,1315 ; C29.2@995,1235 C34.1@1128.5,1235 ; J11.2@1110,1315 1110,1253.5 C34.1@1128.5,1235 ; T1.4@1205,1099.84 1245.16,1099.84 1325,1020 C22.2@1325,980 ; T1.4@1205,1100 1205,1120 1128.5,1196.5 C34.1@1128.5,1235 ; R52.1@4791.02,2285 v1(4855,2285) ; v1(5895,2285) R118.2@5958.98,2285
  MidLayer2 w25: J2.2@560,2160 J2.2@560,2200 560,2325 735,2500 5855,2500 5895,2460 v1(5895,2285) ; v1(4855,2285) 4855,2485
  Bottom Layer w20: D11.1@1215,2185 D11.1@1215,2180.2 1215,2165 1249.8,2130.2 1290,2130.2 ; C49.1@1226.5,1615 1226.5,1651.5 v1(1235,1660) ; C43.2@1235,1938.5 1273.5,1938.5 1290,1955 1290,2130.2 ; v1(1360,2195) 1360,2145.2 1345,2130.2 1290,2130.2
  Bottom Layer w25: J13.2@1010,1320 1002.09,1312.09 C28.2@1002.09,1220 C33.1@1107.91,1220 ; C33.1@1110,1220 C33.1@1107.91,1220 ; J11.2@1110,1320 1107.91,1317.91 C33.1@1107.91,1220 ; R51.1@4791.02,2170 4830,2170 4855,2195 v1(4855,2285)
  other v1: 1040,1725 1080,1725
GND_VSH: C11.2 C12.2 C23.2 C30.2 C31.2 C35.1 C36.1 C39.1 C40.1 C44.2 C46.2 C48.1 C50.1 C52.1 C54.2 C57.1 C58.1 C60.2 D12.1 D14.2 D16.2 D18.1 J4.2 J12.2 J14.2 R10.2 R11.2 R12.1 R39.1 R70.2 R75.1 R76.1 T2.4 U2.8 U8.3 U8.4 U8.9 U10.1 | length 7144.7
  Top Layer w20: D18.1@1512.48,1160 v1(1595,1160) 1595,1165 1620,1140 U2.8@1620,1098.82 ; v1(1595,1235) 1621.5,1261.5 C11.2@1660,1261.5 ; v1(2475,2195) D14.2@2475,2244.52
  Top Layer w25: R11.2@1475,1460 1475,1470 R11.2@1476.42,1470 ; R10.2@1695,1470 1805,1470 1860,1415 R12.1@1860,1326.5 C12.2@1795,1326.5 ; J14.2@2125,1320 2125,1253.5 C31.2@2106.5,1235 C36.1@2248.5,1235 ; J12.2@2225,1320 2225,1258.5 C36.1@2248.5,1235 ; C23.2@2440,980 2440,1020 2360.16,1099.84 T2.4@2320,1099.84 2320,1118.5 2248.5,1190 C36.1@2248.5,1235 ; v1(4155,2285) R70.2@4218.98,2285 ; R76.1@5661.02,2285 v1(5725,2285)
  Bottom Layer w20: D12.1@2330,2185 D12.1@2330,2180.2 2330,2165 2364.8,2130.2 2405,2130.2 ; C50.1@2341.5,1615 2341.5,1651.5 v1(2350,1660) ; C46.2@2350,1938.5 2388.5,1938.5 2405,1955 2405,2130.2 ; v1(2475,2195) 2475,2145.2 2460,2130.2 2405,2130.2
  Bottom Layer w25: J4.2@1677.4,2160 1677.4,2382.4 1795,2500 5645,2500 5725,2420 v1(5725,2285) 5725,2185 5710,2170 R75.1@5661.02,2170 R75.1@5660,2170 ; J14.2@2117.91,1332.09 J14.2@2130,1320 ; J14.2@2127.5,1317.5 2132.09,1312.91 2132.09,1220 C35.1@2222.91,1220 2222.91,1317.91 J12.2@2225,1320 ; v1(4155,2285) 4155,2485
  other v1: 2155,1725 2195,1725
GND_WSH: C20.2 C21.2 C61.2 C71.2 C72.2 C77.1 C78.1 C81.1 C82.1 C85.2 C87.2 C91.1 C93.1 C95.1 C97.2 C99.1 C100.1 C104.2 D25.1 D27.2 D29.2 D32.1 J8.2 J15.2 J17.2 R23.2 R24.2 R29.1 R46.1 R94.2 R99.1 R100.1 T3.4 U4.8 U14.3 U14.4 U14.9 U16.1 | length 6781.5
  Top Layer w20: D32.1@2632.48,1160.31 v1@2715,1160.31 ; v1(2715,1160) 2715,1165.31 2740,1140.31 U4.8@2740,1099.13 ; v1(2715,1235.31) 2741.5,1261.81 C20.2@2780,1261.81 ; v1(3490,2305) 3490,2370 3507.52,2387.52 D27.2@3540,2387.52 D27.2@3545.04,2387.52
  Top Layer w25: R23.2@2815,1470 2925,1470 2980,1415 R29.1@2980,1326.5 ; C21.2@2915,1326.81 R29.1@2980,1326.81 ; C72.2@3216.5,1235 3245,1263.5 J17.2@3245,1315 ; J15.2@3345,1315 3345,1258.5 C78.1@3368.5,1235 ; C78.1@3370,1220 3370,1195 3440,1125 T3.4@3440,1099.84 3480.16,1099.84 3560,1020 C61.2@3560,980 ; v1(5030,2285) R94.2@5088.98,2285 ; R100.1@6535,2285 v1(6535,2450)
  MidLayer1 w25: J8.2@2795.51,2160 2795.51,2405.51 2890,2500 5030,2500 ; v1(5030,2285) 5030,2500 ; v1(6535,2450) 6485,2500 5030,2500
  MidLayer2 w20: 3475,2055 3475,2290 v1(3490,2305)
  Bottom Layer w20: D25.1@3455,2180.2 3455,2295 3465,2305 v1(3490,2305) ; C93.1@3462.3,1615 3462.3,1651.5 v1(3470.8,1660)
  Bottom Layer w25: J17.2@3237.91,1332.09 3245,1325 3345,1325 3342.91,1322.91 J15.2@3342.91,1320 ; C71.2@3242.09,1220 C77.1@3342.91,1220 3342.91,1317.91 J15.2@3345,1320 J15.2@3350,1325 ; R99.1@6531.02,2170 6531.02,2446.02 v1(6535,2450)
  other v1: 3275,1725 3315,1725
NetC4_1: C4.1 D1.3 R1.2 U1.2 | length 320.2
  Top Layer w10: R1.2@810,1265 R1.2@811.5,1263.5
  Top Layer w20: U1.2@805,1098.82 805,1155 811.5,1161.5 C4.1@811.5,1190 811.5,1223.5 v1(810,1225) 815,1230 R1.2@815,1263.5
  Bottom Layer w10: D1.3@681.5,1240 721.16,1240 737.16,1256 779,1256 v1(810,1225)
NetC4_2: C4.2 D2.3 R4.2 U1.3 | length 340.3
  Top Layer w20: R4.2@745,1263.5 745,1228.5 748.5,1225 C4.2@748.5,1190 748.5,1161.5 755,1155 U1.3@755,1100
  Bottom Layer w10: D2.3@681.5,1115 740,1115 750,1125 v1(750,1225)
NetC5_1: C5.1 J3.1 U1.7 | length 391.6
  Top Layer w10: J3.1@357.5,1317.5 J3.1@360,1320
  Top Layer w20: v1(503.5,1198.5) C5.1@545,1198.5 545,1166 555,1156 U1.7@555,1098.82
  Bottom Layer w20: J3.1@355,1320 355,1245 401.5,1198.5 v1(503.5,1198.5)
NetC10_1: C10.1 D3.3 R9.2 U2.2 | length 326
  Top Layer w10: R9.2@1926.5,1263.5 1926.5,1266.5 R9.2@1930,1270
  Top Layer w20: U2.2@1920,1098.82 1920,1155 1926.5,1161.5 C10.1@1926.5,1190 1926.5,1223.5 v1(1925,1225) 1930,1230 R9.2@1930,1263.5
  Bottom Layer w10: D3.3@1796.5,1240 1836.16,1240 1852.16,1256 1894,1256 v1(1925,1225)
NetC10_2: C10.2 D4.3 R12.2 U2.3 | length 331.9
  Top Layer w10: R12.2@1863.5,1258.5 R12.2@1865,1260
  Top Layer w20: R12.2@1860,1263.5 1860,1228.5 1863.5,1225 C10.2@1863.5,1190 1863.5,1161.5 1870,1155 U2.3@1870,1098.82
  Bottom Layer w10: D4.3@1796.5,1115 1835,1115 1865,1145 v1(1865,1225)
NetC11_1: C11.1 J5.1 U2.7 | length 388.1
  Top Layer w20: v1(1618.5,1198.5) C11.1@1660,1198.5 1660,1166 1670,1156 U2.7@1670,1098.82
  Bottom Layer w20: J5.1@1470,1320 1470,1245 1516.5,1198.5 v1(1618.5,1198.5)
NetC14_1: C14.1 R19.2 U3.2 | length 158.5
  Top Layer w10: U3.2@7150,1099.13 7150,1156 7156.5,1162.5 C14.1@7156.5,1190 7156.5,1214.7 7160,1218.2 R19.2@7160,1253.5
NetC14_2: C14.2 R22.2 U3.3 | length 158.5
  Top Layer w10: R22.2@7090,1253.5 7090,1218.2 7093.5,1214.7 C14.2@7093.5,1190 7093.5,1162.5 7100,1156 U3.3@7100,1099.13
NetC16_2: C16.2 R18.2 R19.1 R21.1 | length 285.1
  Top Layer w25: R19.1@7160,1316.5 7160,1346.8 7156.5,1350.3 C16.2@7156.5,1375 7186.02,1404.53 R21.1@7186.02,1475 R18.2@7298.98,1475
NetC17_1: C17.1 D5.3 R20.2 U4.2 | length 318.8
  Top Layer w10: R20.2@3049.25,1264.25 R20.2@3050,1265
  Top Layer w20: U4.2@3040,1099.13 3040,1154.5 3046.5,1161 C17.1@3046.5,1190 3046.5,1223.5 v1(3045,1225) 3050,1230 R20.2@3050,1263.5
  Bottom Layer w10: D5.3@2916.5,1240 2956.16,1240 2972.16,1256 3014,1256 v1(3045,1225)
NetC17_2: C17.2 D6.3 R29.2 U4.3 | length 342.4
  Top Layer w10: R29.2@2983.5,1263.5 2983.5,1268.5 R29.2@2985,1270
  Top Layer w20: R29.2@2980,1263.5 2980,1228.5 2983.5,1225 C17.2@2983.5,1190 2983.5,1161 2990,1154.5 U4.3@2990,1099.13
  Bottom Layer w10: D6.3@2916.5,1115 2965,1115 2985,1135 v1(2985,1225)
NetC18_1: C18.1 J9.1 U3.7 | length 355.7
  Top Layer w20: J9.1@6860,1320 6855,1315 6855,1260 6874,1241 6874,1240.09 6886.5,1227.59 C18.1@6886.5,1190 6886.5,1168.5 6900,1155 U3.7@6900,1100
  Top Layer w25: J9.1@6855,1320 6860,1320 6970,1320
NetC20_1: C20.1 J10.1 U4.7 | length 387.8
  Top Layer w20: v1(2738.5,1198.82) C20.1@2780,1198.82 ; C20.1@2780,1198.5 2780,1166 2790,1156 U4.7@2790,1099.13
  Bottom Layer w20: J10.1@2590,1320 2590,1245 2636.5,1198.5 v1@2738.5,1198.5
NetC42_1: C42.1 R36.1 R38.2 U7.2 | length 242.3
  Bottom Layer w10: U7.2@1047.6,1802 1047.6,1846.1 C42.1@1076.5,1875 1140,1875 R38.2@1165,1850 ; C42.1@1076.5,1881.5 R36.1@1076.5,1940
NetC42_2: C42.2 C47.2 FB1.1 R36.2 U7.1 | length 302.9
  Bottom Layer w10: C47.2@940,1985 965,2010 FB1.1@1013.5,2010 ; C42.2@1010,1875 1015,1870 1015,1840 1022,1833 U7.1@1022,1802 ; C42.2@1013.5,1876.5 R36.2@1013.5,1940 FB1.1@1013.5,2010 ; FB1.1@1015,2015 1013.5,2013.5 FB1.1@1013.5,2010 ; FB1.1@1015.47,2010 FB1.1@1013.5,2010
NetC45_1: C45.1 R37.1 R39.2 U8.2 | length 242.3
  Bottom Layer w10: U8.2@2165,1802 2165,1846.1 2193.9,1875 2257.4,1875 R39.2@2282.4,1850 ; C45.1@2193.9,1881.5 R37.1@2193.9,1940
NetC45_2: C45.2 C48.2 FB2.1 R37.2 U8.1
NetC49_2: C49.2 U7.6 | length 139.1
  Bottom Layer w8: U7.6@1073.2,1648.4 1073.2,1610.8 1083,1601 1115,1601 1132.3,1618.3 C49.2@1163.5,1618.3
NetC50_2: C50.2 U8.6 | length 139.1
  Bottom Layer w8: U8.6@2188.2,1648.4 2188.2,1610.8 2198,1601 2230,1601 2247.3,1618.3 C50.2@2278.5,1618.3
NetC56_2: C56.2 FB3.1 U9.3 | length 228.8
  Bottom Layer w10: FB3.1@540,1740.47 540,1682.09 540,1650 550,1640 625,1640 635,1630 635,1600 U9.3@640,1600
NetC58_2: C58.2 FB4.1 U10.3
NetC86_1: C86.1 R44.1 R46.2 U14.2 | length 242.3
  Bottom Layer w10: U14.2@3283.11,1802 3283.11,1846.1 3312.01,1875 3375.51,1875 R46.2@3400.51,1850 ; C86.1@3312.01,1881.5 R44.1@3312.01,1940
NetC86_2: C86.2 C91.2 FB5.1 R44.2 U14.1
NetC89_1: C89.1 R45.1 R47.2 U15.2 | length 235
  Top Layer w10: R47.2@3860,1915 R47.2@3861.5,1915 R45.1@3938.5,1915 3938.5,1846.5 C89.1@3940,1845 ; C89.1@3938.5,1845 3938.5,1821.5 3957.4,1802.6 U15.2@3957.4,1767
NetC89_2: C89.2 C92.2 FB6.1 R45.2 U15.1 | length 362.5
  Top Layer w10: U15.1@3983,1767 3983,1803 4001.5,1821.5 C89.2@4001.5,1845 ; C89.2@4000,1845 4000,1913.5 R45.2@4001.5,1915 ; R45.2@4000,1915 4032.09,1947.09 C92.2@4032.09,2015 FB6.1@4032.09,2107.91
NetC93_2: C93.2 U14.6 | length 139.1
  Bottom Layer w8: U14.6@3309,1648.4 3309,1610.8 3318.8,1601 3350.8,1601 3368.1,1618.3 C93.2@3399.3,1618.3
NetC94_2: C94.2 U15.6 | length 85.7
  Top Layer w10: U15.6@3931.8,1613.4 3931.8,1571 3932.84,1571 3951,1552.84 3951,1549 C94.2@3960,1540
NetC100_2: C100.2 FB7.1 U16.3
NetC102_2: C102.2 FB8.1 U17.3 | length 209.3
  Bottom Layer w25: FB8.1@7470,1720.47 C102.2@7470,1642.09 7522.91,1642.09 7567.24,1597.76 U17.3@7582.6,1597.76
NetC108_2: C108.2 FB9.1 U18.3 | length 200.8
  Bottom Layer w20: 3785,1600 U18.3@3805,1600
  Bottom Layer w25: FB9.1@3695,1715.47 C108.2@3695,1642.09 3742.91,1642.09 3785,1600
NetC113_1: C113.1 R62.2 R64.1 | length 147.2
  Top Layer w10: R62.2@4286.5,1610 4357.01,1610 4358.5,1608.5 R64.1@4358.5,1545 R64.1@4358.5,1535 ; C113.1@4359.25,1609.25 C113.1@4360,1610
NetC113_2: C113.2 R59.1 U20.2 U20.6 | length 488.1
  Top Layer w10: C113.2@4425,1610 4450,1610 4465,1595 4465,1560 4475,1550 U20.2@4520,1550
  Top Layer w12: U20.2@4520,1550 4580,1550 4630,1500 U20.6@4709,1500 4754.75,1500 4800,1454.75 R59.1@4800,1426.5
NetC114_1: C114.1 D35.3 R56.2 R57.1 U19.1 | length 433.3
  Top Layer w10: R56.2@4535,2170 4531.5,2166.5 C114.1@4531.5,2105 4568.5,2105 D35.3@4588.5,2085 ; U19.1@4540,1958 U19.1@4540,1960 ; U19.1@4540,1975 U19.1@4540,1960 ; U19.1@4540.9,1975.9 4540.9,1958.9 v1(4593.9,1958.9) ; D35.3@4590,2085 4590,2030 4540,1980 U19.1@4540,1960
  Bottom Layer w10: R57.1@4540.9,1927.39 4562.39,1927.39 v1(4593.9,1958.9) v1@4595.9,1960.9
NetC114_2: C114.2 D36.3 R65.1 R66.2 U19.4 | length 450
  Top Layer w10: v1(4407.9,1958.9) 4464.1,1958.9 U19.4@4464.1,1975.9 ; D36.3@4410,2085 4410,2030 U19.4@4463.2,1976.8 ; U19.4@4463.2,1976.8 U19.4@4463.2,1958 4463.2,1960 U19.4@4463.2,1976.8
  Top Layer w12: D36.3@4410,2085 4430,2105 C114.2@4468.5,2105 4465,2108.5 R66.2@4465,2170 ; U19.4@4463.2,1960 U19.4@4465,1960
  Bottom Layer w10: v1@4405.9,1960.9 v1(4407.9,1958.9) 4439.4,1927.39 R65.1@4465.9,1927.39
NetC115_1: C115.1 R60.2 U21.2 | length 164.1
  Top Layer w10: U21.2@4615,1100 4615,1155 4621.5,1161.5 C115.1@4621.5,1190 4621.5,1214.7 4625,1218.2 R60.2@4625,1258.5 ; C115.1@4619.1,1189.1 C115.1@4620.6,1189.1
NetC117_1: C117.1 R64.2 U20.3 | length 171.8
  Top Layer w10: R64.2@4421.5,1545 C117.1@4421.5,1480 4451.02,1480 4471.02,1500 U20.3@4520,1500
NetC118_2: C118.2 R55.2 R62.1 R63.2 R68.1 | length 847.7
  Top Layer w10: R62.1@4223.5,1610 4223.5,1653.5 4235,1665 4340,1665 4358.5,1683.5 4358.5,1713.5 R63.2@4365,1720 ; v1(4305,2015) 4305,1730 4320,1715 R63.2@4358.5,1715
  Bottom Layer w20: v1(4305,2015) 4311.5,2021.5 C118.2@4311.5,2060 4311.5,2080.47 4341.02,2110 R68.1@4341.02,2170 R55.2@4443.98,2170
NetC120_1: C120.1 J20.1 U21.7 | length 353
  Top Layer w10: U21.7@4365,1099.13 U21.7@4365,1105 ; 4432.5,1317.5 4435,1315
  Top Layer w20: U21.7@4365,1105 4365,1155 4351.5,1168.5 C120.1@4351.5,1190 4351.5,1218.5 4320,1250 J20.1@4320,1320 4430,1320
NetC125_1: C125.1 R86.2 R88.1 | length 147.2
  Top Layer w10: R86.2@5156.5,1610 5227.01,1610 5228.5,1608.5 R88.1@5228.5,1545 R88.1@5228.5,1535 ; C125.1@5229.25,1609.25 C125.1@5230,1610
NetC125_2: C125.2 R83.1 U23.2 U23.6 | length 493.5
  Top Layer w10: C125.2@5295,1610 5320,1610 5335,1595 5335,1560 5345,1550 U23.2@5390,1550 5455,1550 5505,1500 U23.6@5579,1500 5640,1500 5670,1470 R83.1@5670,1430
NetC126_1: C126.1 D37.3 R80.2 R81.1 U22.1 | length 464.3
  Top Layer w10: R80.2@5405,2170 5401.5,2166.5 C126.1@5401.5,2105 5440,2105 5460,2085 5460,2025 5410,1975 5410,1960 U22.1@5410,1958 ; U22.1@5410.9,1975.9 5410.9,1958.9 v1(5463.9,1958.9) ; 5458.5,2040.52 D37.3@5458.5,2085
  Bottom Layer w10: R81.1@5410.9,1927.39 5432.39,1927.39 v1(5463.9,1958.9) v1@5465.9,1960.9
NetC126_2: C126.2 D38.3 R89.1 R90.2 U22.4 | length 426.8
  Top Layer w10: v1(5277.9,1958.9) 5334.1,1958.9 U22.4@5334.1,1975.9 ; D38.3@5280.75,2085.75 5300,2105 C126.2@5338.5,2105 5338.5,2168.5 R90.2@5340,2170 ; D38.3@5281.5,2085 5281.5,2028.5 5333.2,1976.8 U22.4@5333.2,1958
  Bottom Layer w10: v1@5275.9,1960.9 v1(5277.9,1958.9) 5309.4,1927.39 R89.1@5335.9,1927.39
NetC127_1: C127.1 R84.2 U24.2 | length 173.5
  Top Layer w10: U24.2@5485,1090 U24.2@5485,1099.13 5485,1155 5490,1160 5490,1190 C127.1@5491.5,1190 ; C127.1@5492.39,1190.9 5492.39,1215.59 5495.9,1219.1 R84.2@5495.9,1259.4
NetC129_1: C129.1 R88.2 U23.3 | length 171.8
  Top Layer w10: R88.2@5291.5,1545 C129.1@5291.5,1480 5321.02,1480 5341.02,1500 U23.3@5390,1500
NetC130_2: C130.2 R79.2 R85.2 R86.1 R92.1 | length 847.7
  Top Layer w10: R86.1@5093.5,1610 5093.5,1653.5 5105,1665 5210,1665 5228.5,1683.5 5228.5,1713.5 R85.2@5235,1720 ; v1(5175,2015) 5175,1730 5190,1715 R85.2@5228.5,1715
  Bottom Layer w20: v1(5175,2015) 5181.5,2021.5 C130.2@5181.5,2060 5181.5,2081.5 5211.02,2111.02 R92.1@5211.02,2170 R79.2@5313.98,2170
NetC132_1: C132.1 J21.1 U24.7 | length 365.8
  Top Layer w10: C132.1@5220,1190 C132.1@5221.5,1188.5 ; C132.1@5221.5,1175 C132.1@5221.5,1188.5 ; C132.1@5221.5,1200 C132.1@5221.5,1190 C132.1@5221.5,1188.5 ; 5305,1315 5310,1320
  Top Layer w20: C132.1@5221.5,1175 5221.5,1168.5 5235,1155 U24.7@5235,1099.13 ; C132.1@5221.5,1200 5221.5,1223.5 5190,1255 J21.1@5190,1320 5300,1320 5305,1315
NetC137_1: C137.1 R110.2 R112.1 | length 147.2
  Top Layer w10: R110.2@6026.5,1610 6097.01,1610 6098.5,1608.5 R112.1@6098.5,1545 R112.1@6098.5,1535 ; C137.1@6099.25,1609.25 C137.1@6100,1610
NetC137_2: C137.2 R107.1 U26.2 U26.6 | length 497.9
  Top Layer w10: C137.2@6165,1610 6190,1610 6205,1595 6205,1560 6215,1550 U26.2@6260,1550 6320,1550 6370,1500 U26.6@6445,1500 ; U26.6@6450,1500 6520,1500 6540,1480 R107.1@6540,1426.5
NetC138_1: C138.1 D39.3 R104.2 R105.1 U25.1 | length 401.2
  Top Layer w10: R104.2@6275,2170 6271.5,2166.5 C138.1@6271.5,2105 6310,2105 D39.3@6329.25,2085.75 ; D39.3@6328.5,2085 6328.5,2023.5 6280,1975 U25.1@6280,1958 v1(6333,1958)
  Bottom Layer w10: R105.1@6280,1926.5 6301.5,1926.5 v1(6333,1958) v1@6335,1960
NetC138_2: C138.2 D40.3 R113.1 R114.2 U25.4 | length 411.7
  Top Layer w10: v1(6147,1958) U25.4@6203.2,1958 6203.2,1975 6151.5,2026.7 D40.3@6151.5,2085 ; D40.3@6150,2085 6170,2105 C138.2@6208.5,2105 6208.5,2166.5 R114.2@6205,2170
  Bottom Layer w10: v1@6145,1960 v1(6147,1958) 6178.5,1926.5 R113.1@6205,1926.5
NetC139_1: C139.1 R108.2 U27.2 | length 163.5
  Top Layer w10: U27.2@6355,1099.13 6355,1155 6361.5,1161.5 C139.1@6361.5,1190 6361.5,1214.7 6365,1218.2 R108.2@6365,1258.5
NetC141_1: C141.1 R112.2 U26.3 | length 171.8
  Top Layer w10: R112.2@6161.5,1545 C141.1@6161.5,1480 6191.02,1480 6211.02,1500 U26.3@6260,1500
NetC142_2: C142.2 R103.2 R109.2 R110.1 R116.1 | length 838.2
  Top Layer w10: R110.1@5963.5,1610 5963.5,1653.5 5975,1665 6080,1665 6098.5,1683.5 R109.2@6098.5,1713.5 ; v1(6045,2015) 6045,1730 6060,1715 R109.2@6098.5,1715 R109.2@6098.5,1713.5 ; R109.2@6100,1715 R109.2@6098.5,1713.5
  Bottom Layer w20: v1(6045,2015) 6051.5,2021.5 C142.2@6051.5,2060 6051.5,2081.5 6081.02,2111.02 R116.1@6081.02,2170 R103.2@6180,2170
NetC144_1: C144.1 J22.1 U27.7 | length 352.2
  Top Layer w10: 6175,1315 6180,1315
  Top Layer w20: 6090,1170 6090,1217.2 6060,1247.2 6060,1310 6070,1320 6175,1320 ; C144.1@6091.5,1190 6091.5,1161.5 6105,1147.99 U27.7@6105,1120
NetD7_2: D7.2 D9.1 T1.6 | length 211.3
  Top Layer w25: T1.6@1005,1099.84 T1.6@1005.16,1100
  Top Layer w32: T1.6@1005.16,1100 1065,1100 ; v1(1065,1075) 1065,1100 ; v1(1065,1125) 1065,1100
  Bottom Layer w25: D7.2@1025,1100 1040,1100 v1(1065,1075) ; v1(1065,1125) 1080.53,1125 D9.1@1105.53,1100
NetD8_2: D8.2 D10.1 T2.6 | length 161.3
  Top Layer w25: T2.6@2120,1099.84 2179.84,1099.84 2180,1100
  Bottom Layer w25: D8.2@2140,1100 2155,1100 v1(2180,1075) ; v1(2180,1125) 2195.53,1125 D10.1@2220.53,1100
NetD13_1: D13.1 R34.1 | length 55.8
  Top Layer w20: R34.1@1305,2311.5 1357.98,2311.5 D13.1@1360,2309.48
